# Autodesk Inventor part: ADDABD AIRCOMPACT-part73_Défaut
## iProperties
Shininess: 64.0
Length Units: 11269
Angle Units: 11279
Time Units: 11290
Mass Units: 11283
Length Display Precision: 3
Angle Display Precision: 2
Compacted: True
Part Number: ADDABD AIRCOMPACT-part73_Défaut
Document SubType Name: Modeling
Created: 2006-01
Material: Par défaut
Designer: riri
Density: 0.0
Volumn: 0.0
Area: 0.0
PropertySet Name: Model Information
Control State: 0
Master: False
Checked Out: False
Author: riri
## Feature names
1. Base1
